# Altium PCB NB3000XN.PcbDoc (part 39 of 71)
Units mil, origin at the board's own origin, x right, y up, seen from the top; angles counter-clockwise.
Board outline 9527.56 x 6929.77 mil, 6 copper layers (Top Layer, GND+SHIELD, MidLayer1, MidLayer2, P2 - 3V3+5V0, Bottom Layer), stack 62.375 mil thick; 832 components, 1027 nets, 4655 pads, 4981 vias.
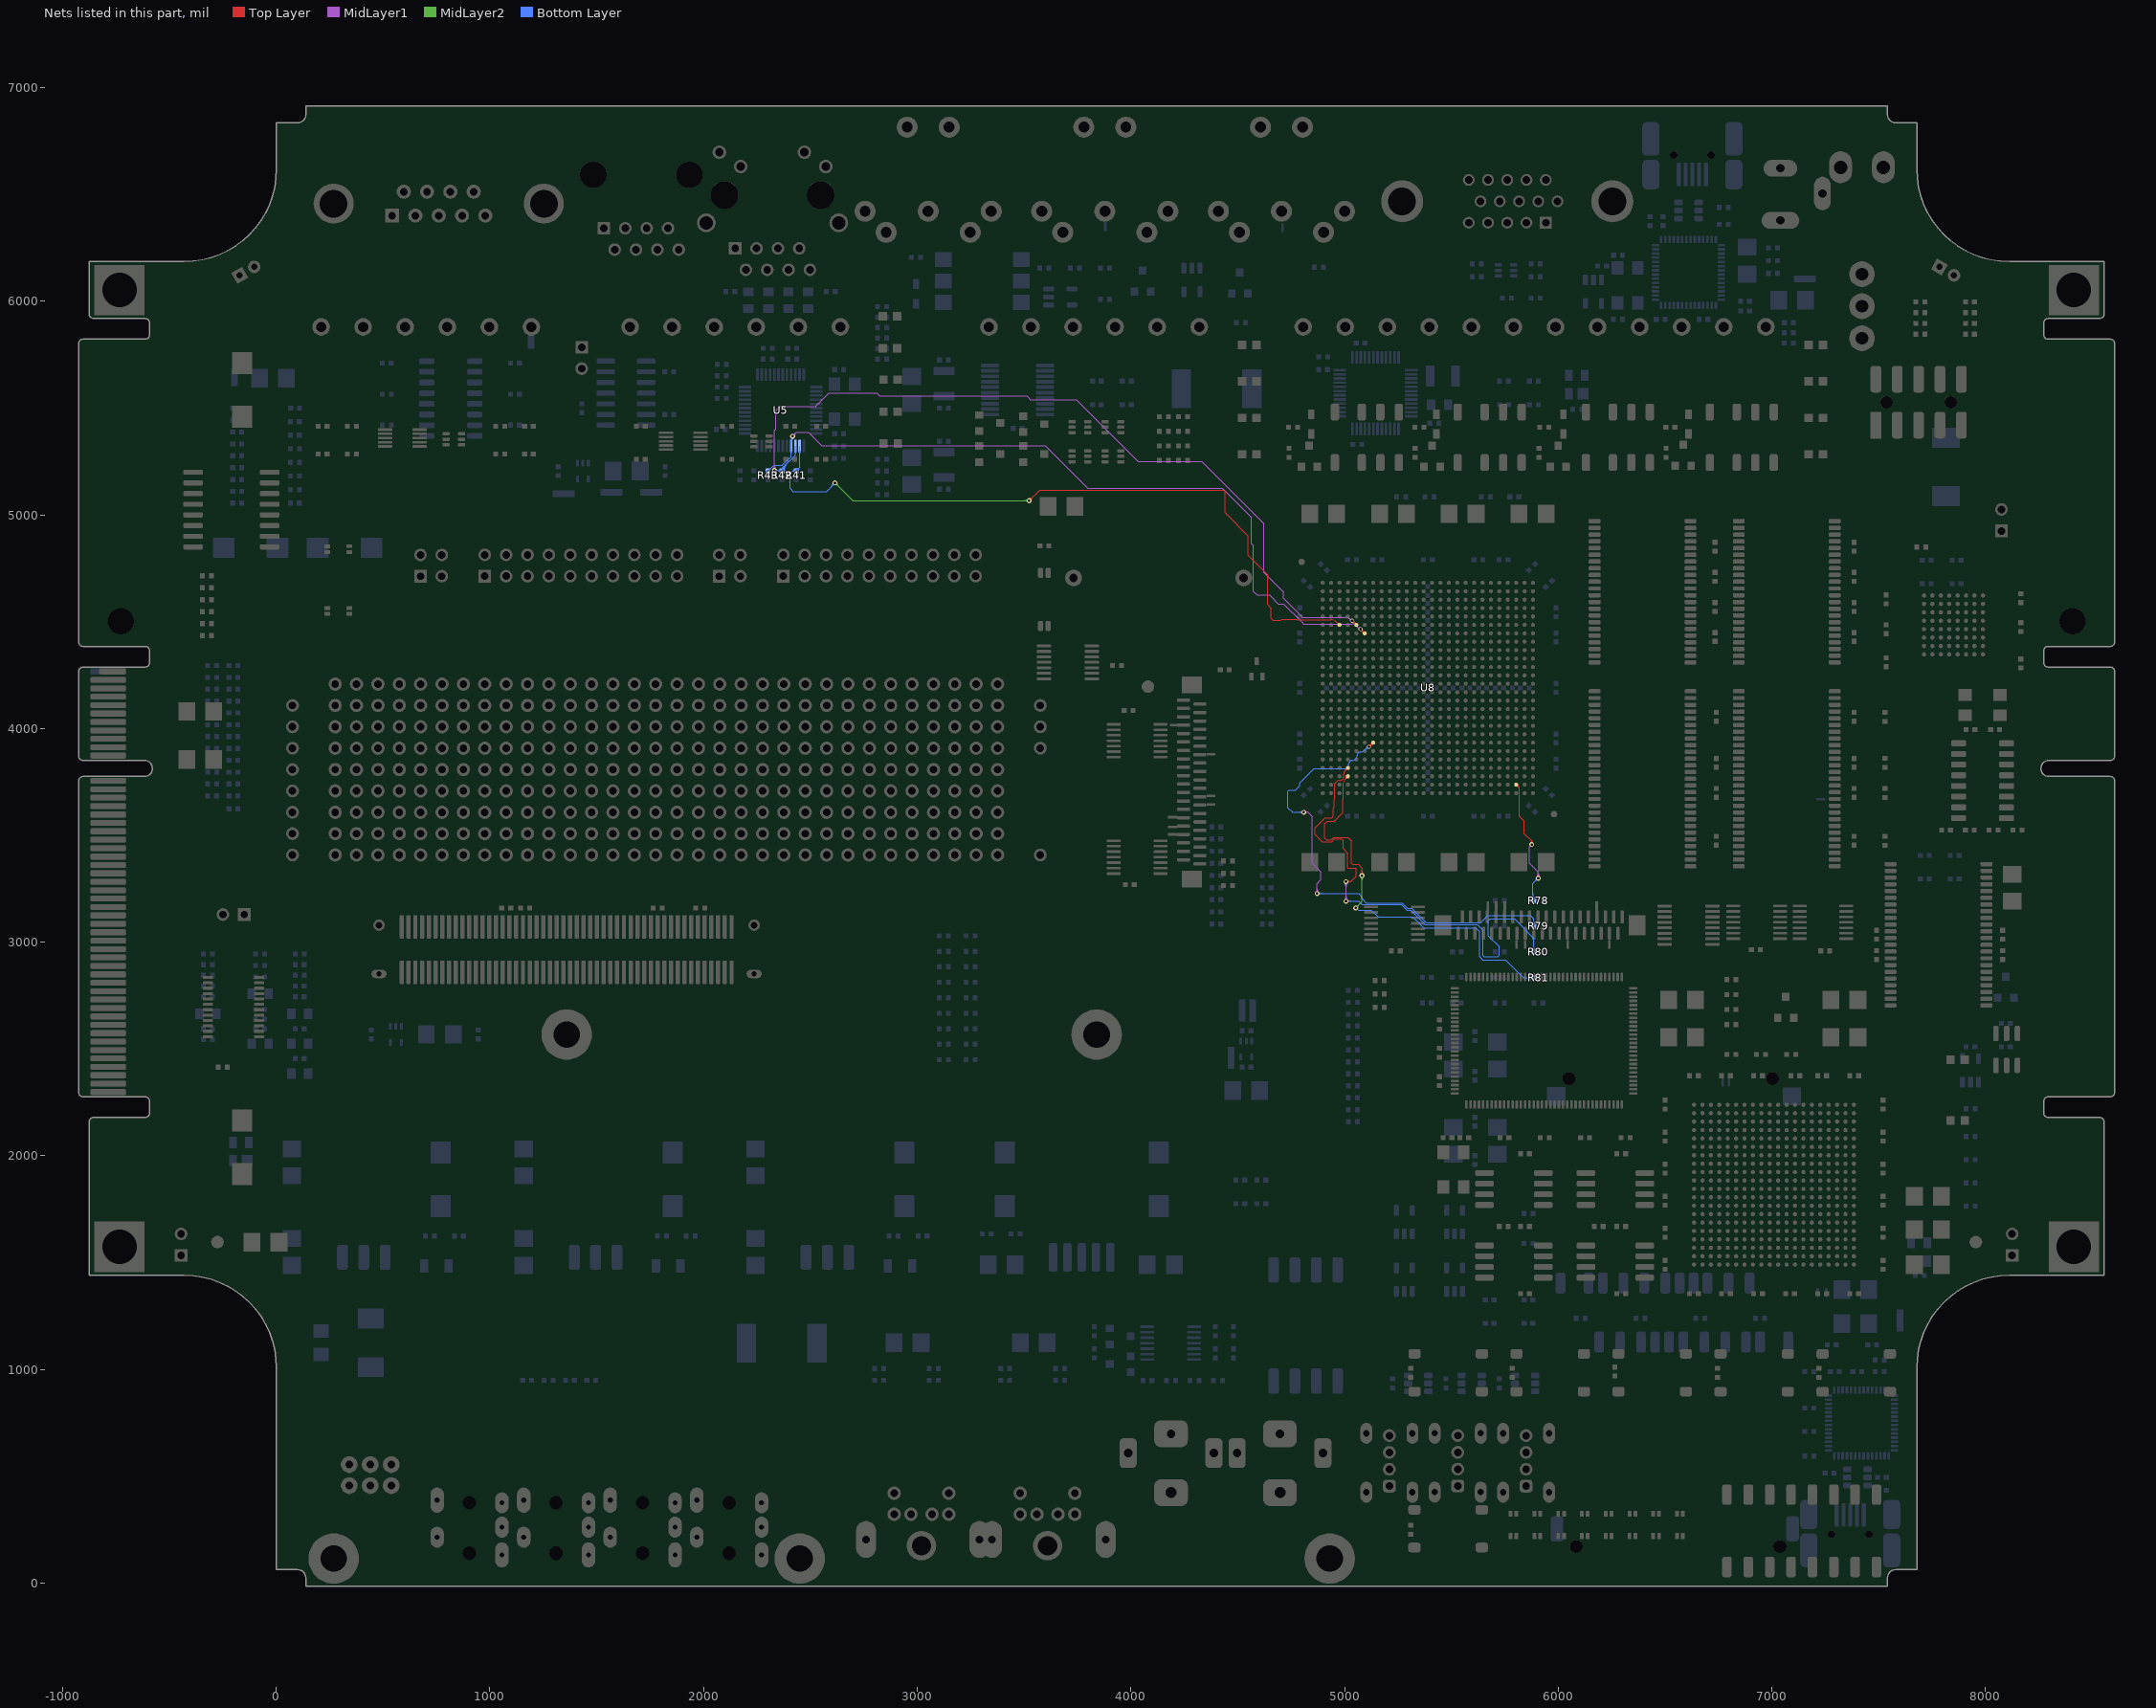
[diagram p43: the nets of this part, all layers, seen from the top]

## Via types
v1: diameter 23, hole 11.81, Top Layer to Bottom Layer, 3672 vias
v2: diameter 26, hole 11.81, Top Layer to Bottom Layer, 461 vias
v3: diameter 19, hole 11.81, Top Layer to Bottom Layer, tented both sides, 396 vias
v4: diameter 23.62, hole 11.81, Top Layer to Bottom Layer, 288 vias
v5: diameter 20, hole 11.81, Top Layer to Bottom Layer, 91 vias
v6: diameter 23, hole 11.81, Top Layer to Bottom Layer, tented both sides, 50 vias
v7: diameter 31, hole 11.81, Top Layer to Bottom Layer, 15 vias
v8: diameter 27.56, hole 11.81, Top Layer to Bottom Layer, tented both sides, 4 vias
v9: diameter 29, hole 11.81, Top Layer to Bottom Layer, 3 vias
v10: diameter 21, hole 11.81, Top Layer to Bottom Layer, 1 vias

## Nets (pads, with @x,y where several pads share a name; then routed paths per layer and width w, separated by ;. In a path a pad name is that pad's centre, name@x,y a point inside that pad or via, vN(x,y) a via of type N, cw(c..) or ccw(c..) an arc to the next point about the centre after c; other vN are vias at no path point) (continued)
ETH.E_TXD2: R43.1 U5.4 U8.G6 | length 3770.4
  Top Layer w4: v3(5075.04,4465.59) U8.G6@5094.72,4445.91 ; U8.G6@5087.22,4445.91 ccw(c5069.12,4445.91) 5081.92,4458.71 ccw(c5094.72,4471.51) U8.G6@5094.72,4453.41 ; U8.G6@5087.38,4445.91 ccw(c5069.66,4445.91) 5082.19,4458.44 ccw(c5094.72,4470.97) U8.G6@5094.72,4453.25 ; 5087.84,4452.79 cw(c5100.65,4465.59) 5082.54,4465.59 ccw(c5100.65,4465.59) 5087.84,4452.79 ; 5087.84,4452.79 ccw(c5075.04,4439.98) 5075.04,4458.09 cw(c5075.04,4439.98) 5087.84,4452.79
  MidLayer1 w4: v1(2416.86,5368.37) 2434.36,5385.87 2491.67,5385.87 2552.5,5325.04 3598.52,5325.04 3798.36,5125.21 4427.42,5125.21 4565,4987.63 4565,4865 4573.52,4856.48 4573.52,4641.71 4590.19,4625.04 4648.52,4625.04 4690.19,4583.37 4715.19,4583.37 4798.56,4500.01 4809.11,4489.45 4860,4489.45 4870,4489.45 4918.62,4489.45 4938.04,4489.45 5012.16,4489.45 ; v1@2416.86,5373.87 ccw(c2416.86,5387.15) 2426.25,5377.76 ccw(c2435.64,5368.37) v1@2422.36,5368.37 ; v1@2416.86,5377.87 ccw(c2416.86,5400.81) 2433.07,5384.59 ccw(c2449.29,5368.37) v1@2426.36,5368.37 ; 4998.23,4489.45 5012.16,4489.45 ; v3@5067.65,4464.29 ccw(c5049.82,4461.14) 5060.21,4475.98 ; v3@5073.74,4472.98 cw(c5070.59,4490.81) 5060.21,4475.98 ; 5012.16,4489.45 5035.41,4489.45 ; 5035.41,4489.45 cw(c5035.41,4465.68) 5035.58,4489.45 ; 5035.41,4489.45 5035.58,4489.45 ; 5035.58,4489.45 cw(c5035.41,4465.68) 5051.63,4483.06 5060.21,4475.98
  Bottom Layer w4: R43.1@2302,5206.18 2329.19,5233.37 2370,5233.37 2370,5233.71 2410.08,5273.79 U5.4@2410.08,5325 ; U5.4@2407.25,5296.32 cw(c2400.41,5289.48) 2410.08,5289.48 ; U5.4@2407.4,5349.17 ccw(c2391.57,5366.71) v1@2415.19,5366.71 ; 2410.08,5289.51 cw(c2419.72,5289.51) U5.4@2412.91,5296.32 ; U5.4@2410.08,5322.68 U5.4@2410.08,5325 ; v1@2410.6,5361.22 cw(c2401.77,5351.12) 2415.19,5351.12 cw(c2424.6,5351.12) v1@2420.75,5359.71 ; v1@2415.19,5357.71 cw(c2399.69,5357.71) U5.4@2410.08,5346.2 ; v1(2416.86,5368.37) v1@2415.19,5366.71 ; U5.4@2410.08,5325 U5.4@2410.08,5346.2 ; U5.4@2410.08,5346.2 2410.19,5346.2 2415.19,5351.2 v1@2415.19,5366.71
ETH.E_TXD3: R42.1 U5.3 U8.F5 | length 4167.2
  Top Layer w4: v3(5035.67,4504.96) U8.F5@5055.35,4485.28 ; U8.F5@5047.85,4485.28 ccw(c5029.75,4485.28) 5042.55,4498.08 ccw(c5055.35,4510.88) U8.F5@5055.35,4492.78 ; U8.F5@5048.01,4485.28 ccw(c5030.29,4485.28) 5042.82,4497.81 ccw(c5055.35,4510.34) U8.F5@5055.35,4492.62 ; 5048.47,4492.16 ccw(c5035.67,4479.35) 5035.67,4497.46 cw(c5035.67,4479.35) 5048.47,4492.16 ; 5048.47,4492.16 cw(c5061.28,4504.96) 5043.17,4504.96 ccw(c5061.28,4504.96) 5048.47,4492.16
  MidLayer1 w4: v1@2325.14,5215.09 ccw(c2308.92,5231.31) 2331.86,5231.31 ccw(c2354.79,5231.31) v1@2338.57,5215.09 ; v1@2327.97,5212.26 ccw(c2318.58,5221.65) 2331.86,5221.65 ccw(c2345.14,5221.65) v1@2335.75,5212.26 ; v1(2331.86,5208.37) 2331.86,5396.67 2337.81,5402.62 2337.81,5487.81 2358.71,5508.71 2523.71,5508.71 2586,5571 2810.5,5571 2825.46,5556.04 3513.96,5556.04 3530,5540 3745,5540 4034.63,5250.37 4331.52,5250.37 4609.25,4972.65 4623.19,4958.71 4623.19,4729.69 4714.86,4638.02 4714.86,4609.36 4803.74,4520.47 4855.26,4520.47 4860,4520.47 4870,4520.47 4918.62,4520.47 5002.99,4520.47 cw(c5003.16,4487.34) 5020.81,4515.38 ; v3@5028.28,4503.66 ccw(c5010.45,4500.51) 5020.84,4515.35 ccw(c5031.22,4530.18) v3@5034.37,4512.35
  Bottom Layer w4: v1(2331.86,5208.37) 2347.86,5208.37 ; v1@2340.2,5203.83 cw(c2347.86,5199.65) 2347.86,5208.37 ; v1@2340.2,5212.92 ccw(c2347.86,5217.1) 2347.86,5208.37 ; R42.1@2359.76,5201 ccw(c2350.05,5194.49) 2350.05,5206.18 ; R42.1@2359.76,5211.37 cw(c2350.05,5217.87) 2350.05,5206.18 ; R42.1@2365.81,5206.18 cw(c2389.06,5206.18) 2372.62,5222.62 ; R42.1@2369.81,5206.18 cw(c2402.72,5206.18) 2379.45,5229.45 ; R42.1@2373.81,5206.18 cw(c2416.37,5206.18) 2386.28,5236.28 ; R42.1@2377.81,5206.18 cw(c2430.03,5206.18) 2393.11,5243.11 ; U5.3@2426.94,5296.32 cw(c2420.11,5289.49) 2429.76,5289.49 cw(c2439.42,5289.49) U5.3@2432.59,5296.32 ; U5.3@2429.76,5322.68 2429.76,5279.76 2368,5218 R42.1@2368,5206.18 2350.05,5206.18 ; 2347.86,5208.37 2350.05,5206.18
ETH.E_TXEN: R41.1 U5.2 U8.F3 | length 3827.7
  Top Layer w4: v1(3523.52,5066.71) 3573.52,5116.71 4431.86,5116.71 4440.19,5108.37 4440.19,5009.81 ; v1@3523.52,5072.21 ccw(c3523.52,5085.49) 3532.91,5076.1 ccw(c3542.3,5066.71) v1@3529.02,5066.71 ; v1@3523.52,5076.21 ccw(c3523.52,5099.14) 3539.74,5082.93 ccw(c3555.96,5066.71) v1@3533.02,5066.71 ; 4448.41,5001.59 4440.19,5009.81 ; 4440.19,5009.81 4548.52,4901.48 4548.52,4810.75 4640.19,4719.08 4640.19,4580.39 4656.86,4563.73 4656.86,4516.04 4665.52,4507.37 4665.62,4507.47 4701.91,4507.47 4706.81,4512.37 4758,4512.37 4775.03,4512.37 4778.27,4509.14 4796.07,4509.14 ; 4796.07,4509.14 4821,4509.14 ; 4796.07,4509.14 4821,4509.14 ; 4821,4509.14 4856.86,4509.14 ; 4856.86,4509.14 4855.26,4509.14 4856.86,4509.14 ; 4856.86,4509.14 4860,4509.14 4870,4509.14 4886.05,4509.14 4936.73,4509.14 ; 4936.73,4509.14 cw(c4936.73,4470.46) 4964.08,4497.81 ; 4936.73,4509.14 cw(c4936.73,4470.46) 4964.08,4497.81 ; 4964.08,4497.81 ccw(c4976.61,4510.34) 4976.61,4492.62 cw(c4976.61,4510.34) 4964.08,4497.81 ; 4964.08,4497.81 cw(c4951.55,4485.28) 4969.27,4485.28 ccw(c4951.55,4485.28) 4964.08,4497.81
  MidLayer2 w4: v1@2615.19,5140.54 cw(c2615.19,5117.61) 2631.41,5133.82 cw(c2647.63,5150.04) v1@2624.69,5150.04 ; v1@2615.19,5144.54 cw(c2615.19,5131.26) 2624.58,5140.65 cw(c2633.97,5150.04) v1@2620.69,5150.04 ; v1(2615.19,5150.04) 2698.52,5066.71 v1(3523.52,5066.71) ; v1@3516.81,5059.99 ccw(c3500.59,5043.77) 3500.59,5066.71 ccw(c3500.59,5089.64) v1@3516.81,5073.43 ; v1@3519.64,5062.82 ccw(c3510.25,5053.43) 3510.25,5066.71 ccw(c3510.25,5079.99) v1@3519.64,5070.6
  Bottom Layer w4: R41.1@2425.73,5201.04 ccw(c2416.18,5194.73) 2416.18,5206.18 ; R41.1@2425.73,5211.32 cw(c2416.18,5217.63) 2416.18,5206.18 ; R41.1@2434.52,5211.5 ccw(c2434.58,5222.94) R41.1@2442.67,5214.85 ; R41.1@2434.54,5215.5 ccw(c2434.65,5236.43) 2449.45,5221.63 ccw(c2463.18,5207.9) R41.1@2443.79,5206.74 ; R41.1@2439.8,5206.5 cw(c2451.31,5207.19) R41.1@2443.16,5215.34 ; U5.2@2446.62,5296.32 cw(c2439.79,5289.49) 2449.45,5289.49 cw(c2459.11,5289.49) U5.2@2452.28,5296.32 ; U5.2@2449.44,5299.15 2449.45,5320.32 U5.2@2449.45,5299.15 ; U5.2@2449.45,5322.68 U5.2@2449.45,5299.15 ; v1@2605.69,5150.04 cw(c2582.76,5150.04) 2598.97,5133.82 cw(c2615.19,5117.61) v1@2615.19,5140.54 ; v1@2609.69,5150.04 cw(c2596.41,5150.04) 2605.8,5140.65 cw(c2615.19,5131.26) v1@2615.19,5144.54 ; v1(2615.19,5150.04) 2575.15,5110 2420,5110 2405,5125 2405,5195 2416.18,5206.18 ; 2416.18,5206.18 R41.1@2434,5206.18 2449.45,5221.63 U5.2@2449.45,5299.15
FPGA_CCLK#: R78.2 U8.AE24 | length 864
  Top Layer w4: v1@5871.35,3465.55 ccw(c5866.32,3474.04) 5876.19,3474.04 ; v1(5876.19,3457.37) 5876.19,3474.04 ; v1@5881.03,3465.55 cw(c5886.06,3474.04) 5876.19,3474.04 ; 5815.92,3724.71 cw(c5808.74,3717.53) 5818.89,3717.53 ; 5815.92,3724.71 cw(c5808.74,3717.53) 5818.89,3717.53 ; 5815.92,3724.71 ccw(c5803.39,3712.17) 5803.39,3729.9 cw(c5803.39,3712.17) 5815.92,3724.71 ; 5815.92,3724.71 cw(c5828.45,3737.24) 5810.73,3737.24 ccw(c5828.45,3737.24) 5815.92,3724.71 ; 5818.89,3717.53 5818.89,3670 5818.89,3660 5818.89,3587.83 5818.86,3587.79 5841.02,3565.62 5841.02,3509.21 5841.86,3508.37 5876.19,3474.04
  MidLayer1 w4: v1(5876.19,3457.37) 5865.19,3446.37 5865.19,3435 5865.19,3369.81 5906.86,3328.14 v1(5906.86,3300.04) ; v1@5900.14,3306.76 ccw(c5883.92,3322.98) 5906.86,3322.98 ccw(c5929.79,3322.98) v1@5913.57,3306.76 ; v1@5902.97,3303.93 ccw(c5893.58,3313.32) 5906.86,3313.32 ccw(c5920.14,3313.32) v1@5910.75,3303.93
  Bottom Layer w4: R78.2@5879.23,3202.08 ccw(c5872.89,3208.43) 5881.86,3208.43 ; 5881.86,3208.24 ccw(c5898.57,3208.24) R78.2@5886.75,3196.42 ; 5881.86,3217.9 ccw(c5908.22,3217.9) R78.2@5889.58,3199.25 ; 5881.86,3227.55 ccw(c5917.88,3227.55) R78.2@5892.41,3202.08 ; R78.2@5885.82,3195 5885.82,3191.71 5881.86,3191.71 5881.86,3195 5881.86,3275.04 v1(5906.86,3300.04) ; v1@5897.36,3300.04 cw(c5874.42,3300.04) 5890.64,3283.82 cw(c5906.86,3267.61) v1@5906.86,3290.54 ; v1@5901.36,3300.04 cw(c5888.08,3300.04) 5897.47,3290.65 cw(c5906.86,3281.26) v1@5906.86,3294.54
FPGA_M0#: R81.2 U8.AD4 | length 2191.8
  Top Layer w4: v1@5075.14,3318.43 ccw(c5058.92,3334.64) 5081.86,3334.64 ccw(c5104.79,3334.64) v1@5088.57,3318.43 ; v1@5077.97,3315.6 ccw(c5068.58,3324.99) 5081.86,3324.99 ccw(c5095.14,3324.99) v1@5085.75,3315.6 ; v1(5081.86,3311.71) 5081.86,3347.37 5065.19,3364.04 5038.19,3364.04 5032.19,3370.04 5032.19,3475.04 5016.86,3490.37 4948.52,3490.37 4936.86,3478.71 4915.19,3478.71 4906.86,3487.04 4906.86,3554.04 4919.52,3566.71 4951.52,3566.71 4992.12,3607.31 4992.12,3660 4992.12,3670 4992.12,3736.73 ; 4992.12,3736.73 cw(c5030.8,3736.73) 5003.45,3764.08 ; 4992.12,3736.73 cw(c5030.8,3736.73) 5003.45,3764.08 ; 5003.45,3764.08 ccw(c4990.92,3776.61) 5008.64,3776.61 cw(c4990.92,3776.61) 5003.45,3764.08 ; 5003.45,3764.08 cw(c5015.98,3751.55) 5015.98,3769.27 ccw(c5015.98,3751.55) 5003.45,3764.08
  MidLayer2 w4: v1@5051.86,3165.87 ccw(c5051.86,3179.15) 5061.25,3169.76 ccw(c5070.64,3160.37) v1@5057.36,3160.37 ; v1@5051.86,3169.87 ccw(c5051.86,3192.81) 5068.07,3176.59 ccw(c5084.29,3160.37) v1@5061.36,3160.37 ; v1@5060.19,3160.37 v1(5051.86,3160.37) 5082.36,3190.87 5082.36,3311.21 v1(5081.86,3311.71) ; v1@5075.14,3304.99 cw(c5057.72,3287.57) 5082.36,3287.57 ; v1@5077.97,3307.82 cw(c5067.37,3297.22) 5082.36,3297.22 ; 5082.36,3289.98 cw(c5103.59,3289.98) v1@5088.57,3304.99 ; 5082.36,3299.64 cw(c5093.93,3299.64) v1@5085.75,3307.82
  Bottom Layer w4: v1(5051.86,3160.37) 5054.86,3160.37 5065.19,3150.04 5125.13,3150.04 5157.8,3117.37 5319.88,3117.37 5370.54,3066.71 5615.19,3066.71 5631.86,3050.04 5631.86,2931.83 5646.69,2917 5680,2917 5709.56,2917 5753.58,2917 5837.21,2833.37 5885.82,2833.37 5885.82,2834.51 R81.2@5885.82,2835 ; 5860.59,2833.37 ccw(c5860.59,2859.74) R81.2@5879.23,2841.1 ; 5866.06,2833.37 cw(c5866.06,2814.75) R81.2@5879.23,2827.92 ; 5870.24,2833.37 ccw(c5870.24,2850.08) R81.2@5882.06,2838.27
FPGA_M1#: R80.2 U8.AC4 | length 2652.2
  Top Layer w4: v1(5006.86,3283.37) 5029.52,3283.37 ; v1@5010.78,3279.52 cw(c5019.98,3270.47) 5019.98,3283.37 cw(c5019.98,3296.28) v1@5010.78,3287.23 ; v1@5013.63,3276.71 cw(c5029.52,3261.09) 5029.52,3283.37 ; v1@5013.63,3290.04 ccw(c5029.52,3305.66) 5029.52,3283.37 ; 5003.45,3803.45 ccw(c4990.92,3815.98) 5008.64,3815.98 cw(c4990.92,3815.98) 5003.45,3803.45 ; 5003.45,3803.45 cw(c5015.98,3790.92) 5015.98,3808.64 ccw(c5015.98,3790.92) 5003.45,3803.45 ; 5003.45,3803.45 5002.06,3802.06 5002.06,3801.97 ccw(c5015.98,3788.06) 4996.3,3788.06 4996.3,3776.61 cw(c4976.61,3776.62) 4976.61,3756.93 ccw(c4976.61,3737.24) 4963.64,3752.05 4955.73,3744.13 4955.73,3743.91 ccw(c4962.9,3736.73) 4952.75,3736.73 4952.75,3670 4952.75,3660 4952.75,3632.69 4946.36,3626.29 4946.36,3588.11 4940.96,3582.71 4909.86,3582.71 4862.32,3535.17 4862.32,3504.25 4895.86,3470.71 4940.17,3470.71 4951.84,3482.37 4985,3482.37 4993.86,3473.52 4993.86,3438.04 5015.19,3416.71 5015.19,3350.04 5017.52,3347.71 5052.19,3347.71 5054.86,3345.04 5054.86,3308.71 5029.52,3283.37
  MidLayer1 w4: v1@5000.14,3198.43 ccw(c4983.92,3214.64) 5006.86,3214.64 ccw(c5029.79,3214.64) v1@5013.57,3198.43 ; v1@5000.14,3276.66 cw(c4983.92,3260.44) 5006.86,3260.44 cw(c5029.79,3260.44) v1@5013.57,3276.66 ; v1@5002.97,3195.6 ccw(c4993.58,3204.99) 5006.86,3204.99 ccw(c5020.14,3204.99) v1@5010.75,3195.6 ; v1@5002.97,3279.49 cw(c4993.58,3270.1) 5006.86,3270.1 cw(c5020.14,3270.1) v1@5010.75,3279.49 ; v1(5006.86,3191.71) v1(5006.86,3283.37)
  Bottom Layer w4: v1(5006.86,3191.71) 5065.19,3191.71 5080.86,3176.04 5265.86,3176.04 5291.86,3150.04 5311.19,3150.04 5377.86,3083.37 5621.15,3083.37 5648.52,3056 5648.52,2977.04 ; v1@5010.75,3187.82 cw(c5020.14,3178.43) 5020.14,3191.71 cw(c5020.14,3204.99) v1@5010.75,3195.6 ; v1@5013.57,3184.99 cw(c5029.79,3168.77) 5029.79,3191.71 cw(c5029.79,3214.64) v1@5013.57,3198.43 ; 5648.19,2996.81 5648.19,2938.12 5652.94,2933.37 5718.52,2933.37 5723.52,2938.37 5723.52,2978.71 5673.52,3028.71 5673.52,3100.04 5681.86,3108.37 5755,3108.37 5790.19,3108.37 5795.54,3108.37 5885.82,3018.1 5885.82,3012.75 R80.2@5885.82,2955.49 ; R80.2@5879.23,2962.08 ccw(c5863.32,2977.99) 5885.82,2977.99 ccw(c5908.32,2977.99) R80.2@5892.41,2962.08 ; R80.2@5882.06,2959.25 ccw(c5872.98,2968.33) 5885.82,2968.33 ccw(c5898.66,2968.33) R80.2@5889.58,2959.25 ; R80.2@5890.19,2955.49 R80.2@5885.82,2955.49 ; R80.2@5885.82,2955.07 R80.2@5885.82,2955 R80.2@5885.82,2955.07 ; R80.2@5885.82,2955.07 R80.2@5885.82,2955.49 ; R80.2@5885.82,2955.07 R80.2@5885.82,2955.49
FPGA_M2#: R79.2 U8.Y7 | length 2622.4
  Top Layer w4: v3(5114.41,3914.41) U8.Y7@5134.09,3934.09 ; U8.Y7@5126.59,3934.09 cw(c5108.49,3934.09) 5121.29,3921.29 cw(c5134.09,3908.49) U8.Y7@5134.09,3926.59 ; U8.Y7@5126.75,3934.09 cw(c5109.03,3934.09) 5121.56,3921.56 cw(c5134.09,3909.03) U8.Y7@5134.09,3926.75 ; 5127.21,3927.21 cw(c5114.41,3940.02) 5114.41,3921.91 ccw(c5114.41,3940.02) 5127.21,3927.21 ; 5127.21,3927.21 ccw(c5140.02,3914.41) 5121.91,3914.41 cw(c5140.02,3914.41) 5127.21,3927.21
  MidLayer1 w4: v1(4808.86,3608.37) 4829.19,3608.37 ; v1@4813.08,3604.85 cw(c4820.63,3598.53) 4820.63,3608.37 cw(c4820.63,3618.22) v1@4813.08,3611.9 ; v1@4816.14,3602.28 cw(c4829.19,3591.37) 4829.19,3608.37 ; v1@4816.14,3614.47 ccw(c4829.19,3625.38) 4829.19,3608.37 ; v1@4865.14,3234.09 ccw(c4848.92,3250.31) 4871.86,3250.31 ccw(c4894.79,3250.31) v1@4878.57,3234.09 ; v1@4867.97,3231.26 ccw(c4858.58,3240.65) 4871.86,3240.65 ccw(c4885.14,3240.65) v1@4875.75,3231.26 ; v1(4871.86,3227.37) 4871.86,3273.71 4890.19,3292.04 4890.19,3328.02 4849.19,3369.02 4849.19,3430 4849.19,3588.37 4829.19,3608.37
  Bottom Layer w4: v1@4801.72,3602.1 ccw(c4787.86,3589.92) 4787.86,3608.37 ; v1@4801.72,3614.65 cw(c4787.86,3626.83) 4787.86,3608.37 ; v1@4804.73,3604.74 ccw(c4796.7,3597.69) 4796.7,3608.37 ccw(c4796.7,3619.06) v1@4804.73,3612.01 ; v1(4808.86,3608.37) 4787.86,3608.37 ; v1(4871.86,3227.37) 5065.19,3227.37 5081.86,3210.71 5081.86,3205 5102.82,3184.04 5269.17,3184.04 5294.84,3158.37 5314.17,3158.37 5380.84,3091.71 5636.67,3091.71 5670,3125.04 5869.96,3125.04 5885.82,3109.18 R79.2@5885.82,3075 ; v1@4875.75,3223.49 cw(c4885.14,3214.1) 4885.14,3227.37 cw(c4885.14,3240.65) v1@4875.75,3231.26 ; v1@4878.57,3220.66 cw(c4894.79,3204.44) 4894.79,3227.37 cw(c4894.79,3250.31) v1@4878.57,3234.09 ; v3@5107.02,3915.71 cw(c5089.19,3918.86) 5099.58,3904.02 ; v3@5113.11,3907.02 ccw(c5109.96,3889.19) 5099.58,3904.02 ; R79.2@5879.23,3082.08 ccw(c5863.32,3097.99) 5885.82,3097.99 ccw(c5908.32,3097.99) R79.2@5892.41,3082.08 ; R79.2@5882.06,3079.25 ccw(c5872.98,3088.33) 5885.82,3088.33 ccw(c5898.66,3088.33) R79.2@5889.58,3079.25 ; 4787.86,3608.37 4756.63,3608.37 4735,3630 4735,3706.54 4740.5,3712.04 4771.19,3712.04 4790.19,3731.04 4790.19,3745.19 4856.9,3811.9 4860,3811.9 4870,3811.9 4879.78,3811.9 4938.04,3811.9 4996.3,3811.9 ccw(c4996.3,3835.67) 5020.07,3835.67 cw(c5035.67,3835.67) 5035.67,3851.27 ccw(c5035.67,3875.04) 5059.44,3875.04 cw(c5075.04,3875.04) 5075.04,3890.64 ccw(c5075.04,3914.41) 5091.85,3897.6 5099.58,3904.02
